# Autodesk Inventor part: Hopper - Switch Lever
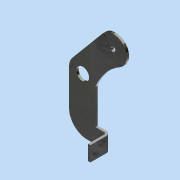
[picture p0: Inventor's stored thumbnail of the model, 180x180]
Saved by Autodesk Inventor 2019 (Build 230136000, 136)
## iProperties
Created: 2005-11
Part Number: Hopper - Switch Lever
Document SubType Name: Sheet Metal
Designer: floress
Material: Steel, Mild
Density: 7.85 g/cm^3
Sheet Metal Rule: Default
Appearance: Semi-Polished
Flat Pattern Width: 2.83459 cm
Flat Pattern Length: 3.63985 cm
Flat Pattern Area: 10.3175 cm^2
Sheet Metal Width: 1.116 in
Sheet Metal Length: 1.433 in
Sheet Metal Area: 1.599 in^2
Author: floress
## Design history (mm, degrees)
node "Face2"
  sketch "Sketch1"
    geometry: L1 (-65.691, 38.749)-(-55.039, 51.449); L2 (-62.042, 35.688)-(-66.804, 35.688); L3 (-66.804, 35.688)-(-66.804, 16.638); L4 (-66.804, 16.638)-(-53.003, 16.638); L5 (-57.571, 34.048)-(-57.571, 21.872); L6 (-53.003, 16.638)-(-53.003, 21.872); L7 (-53.003, 21.872)-(-57.571, 21.872); C1 r 2.216 at (-62.042, 35.688) reference; C2 r 2.216 at (-62.042, 35.688); C3 r 0.794 at (-51.39, 48.388); A1 r 3.175 centre (-51.39, 48.388) between (-53.43, 45.956) and (-49.35, 50.821) reference; A2 r 4.763 centre (-51.39, 48.388) between (-48.996, 44.271) and (-55.039, 51.449); A3 r 4.763 centre (-62.042, 35.688) between (-65.691, 38.749) and (-66.804, 35.688); A4 r 19.656 centre (-39.117, 27.278) between (-48.996, 44.271) and (-57.571, 34.048)
    constraints: 14 end point, 6 point on circle, 5 centre point, 5 tangent, 4 coincident, 3 perpendicular, 1 concentric, 1 horizontal, 1 parallel
    dimensions: "d0" = 9.525 diameter of A2; "d1" = 9.525 diameter of A3; "d2" = 19.05 distance of L2.end L3.end; "d4" = 1.5875 diameter of C3
node "Flange1"
feature "Corner Round1" dims "d13" = 6.35
body "Solid1"
node "Reference1"
node "Reference2"
face "Plate2" dims "d14" = 0.79375 (= Thickness)
sketch "Sketch2"
  geometry: L1 through (2.617, 0) direction (1, 0); L2 (5.233, 0)-(5.233, 6.35); L3 (5.233, 6.35)-(0, 6.35); L4 through (0, 3.175) direction (0, -1)
  constraints: 6 end point, 1 horizontal, 1 perpendicular, 1 vertical
face "Plate3" dims "d6" = 0.79375 (= BendReliefWidth), "d8" = 1.5875 (= MinimumRemnant), "d10" = 6.35, "d11" = 90 deg, "d12" = 0.79375 (= BendRadius), "d14" = 0.79375 (= Thickness)
bend "Bend1" dims "d6" = 0.79375 (= BendReliefWidth), "d7" = 0.39687 (= BendReliefDepth), "d8" = 1.5875 (= MinimumRemnant), "d9" = 0.79375 (= BendRadius), "d10" = 6.35, "d11" = 90 deg, "d12" = 0.79375 (= BendRadius), "d14" = 0.79375 (= Thickness), "SeamGap" = 0.00508
feature "Definition1"
other parameters: "Thickness" = 0.79375, "BendRadius" = 0.79375 (= Thickness), "BendReliefWidth" = 0.79375 (= Thickness), "BendReliefDepth" = 0.39687 (= 0.5 x Thickness), "CornerReliefSize" = 3.175 (= 4 x Thickness), "MinimumRemnant" = 1.5875 (= 2 x Thickness), "TransitionRadius" = 0.79375 (= BendRadius), "d3" = 0.79375 (= BendRadius), "d5" = 0.79375 (= BendRadius), "JacobiRadiusSize" = 0.79375 (= Thickness), "GapSize" = 0.79375 (= Thickness), "BendRadius" = 0.79375, "BendReliefDepth" = 0.39687, "BendReliefWidth" = 0.79375, "CornerReliefSize" = 3.175, "GapSize" = 0.79375, "JacobiRadiusSize" = 0.79375, "MinimumRemnant" = 1.5875, "Thickness" = 0.79375, "TransitionRadius" = 0.79375
